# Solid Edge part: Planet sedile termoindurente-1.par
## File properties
Author: s.pallini
Template: Normal.par
Last saved by: s.pallini
Revision: 8
Application: Solid Edge
Precisione: 0,990
Tipo di contenuto documento: 0
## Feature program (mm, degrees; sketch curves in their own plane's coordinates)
sketch for "ProtrusioneEstrusa_1" plane through (0, 0, 0) normal (0, -1, 0) x-axis (1, 0, 0)
  line (-132, -255) -> (132, -255)
  line (132, -255) -> (132, -173.3751)
  arc centre (139.5779, -173.3751) radius 7.5779 from (134.8258, -167.4724) to (132, -173.3751) ccw
  arc centre (-139.5779, -173.3751) radius 7.5779 from (-132, -173.3751) to (-134.8258, -167.4724) ccw
  line (-132, -255) -> (-132, -173.3751)
  dimension (linear) = 132
extrude "ProtrusioneEstrusa_1" add finite 50 along -normal
draft "Draft_1"  Angles1 = 10 deg
thinwall "Thinwall_1"  Thickness = 5 mm
fillet "Rotondo_1" radius 5
fillet "Rotondo_2" radius 3
sketch for "ExtrudedProtrusion_2" #1 plane through (0, 5, -36.5059) normal (0, 1, 0) x-axis (-1, 0, 0)
  line (13.9982, -218.4941) -> (13.9982, -188.4941)
  line (13.9982, -188.4941) -> (48.9982, -188.4941)
  line (48.9982, -188.4941) -> (48.9982, -218.4941)
  line (48.9982, -218.4941) -> (13.9982, -218.4941)
sketch for "ExtrudedProtrusion_2" #2 plane through (0, 5, -36.5059) normal (0, 1, 0) x-axis (-1, 0, 0)
  line (-45.0018, -218.4941) -> (-45.0018, -188.4941)
  line (-45.0018, -188.4941) -> (-10.0018, -188.4941)
  line (-10.0018, -188.4941) -> (-10.0018, -218.4941)
  line (-10.0018, -218.4941) -> (-45.0018, -218.4941)
  dimension (linear) = 45.0018
extrude "ExtrudedProtrusion_2" add finite 35 along +normal
fillet "Rotondo_3" radius 15
sketch for "ExtrudedProtrusion_3" #1 plane through (0, 5, -36.5059) normal (0, 1, 0) x-axis (0, 0, -1)
sketch for "ExtrudedProtrusion_3" #2 plane through (0, 5, -36.5059) normal (0, 1, 0) x-axis (0, 0, -1)
extrude "ExtrudedProtrusion_3" add finite 15 along +normal
fillet "Rotondo_4" radius 5
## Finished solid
Body 1: solid body, 45 faces, 101 edges, 58 vertices.
  Faces by surface: plane 16, torus 12, cylinder 11, cone 6
  Edges by curve: line 51, circle 48, ellipse 2
Bounding box of the edges (mm; curved faces can reach further): 428.758 x 50.000 x 469.379, from (-214.3792, 0, -255) to (214.3792, 50, 214.3792).
Cylindrical faces by radius (mm): R3 x5, R5 x2, R7.5 x2, R15 x2
Conical faces (half-angle, radius in mm at the cone's reference point): 10 deg R7.5779 x2, 10 deg R12.5019 x2, 10 deg R210.076 x1, 10 deg R215 x1
Toroidal faces (ring radius, tube radius in mm): R2 r3 x2, R2.5 r5 x2, R11.1531 r3 x2, R12.5 r5 x2, R20.5897 r5 x2, R201.9882 r5 x1, R211.4247 r3 x1
Planar faces by outward normal: +x 2, +y 4, +z 2, -x 2, -y 1, -z 1, oblique 4
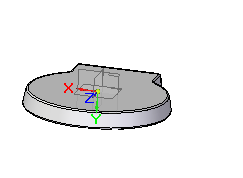
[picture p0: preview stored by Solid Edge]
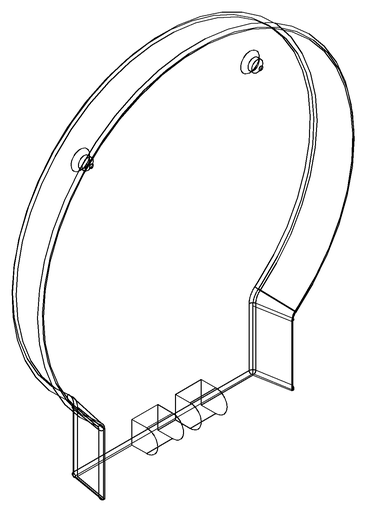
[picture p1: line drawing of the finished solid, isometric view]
